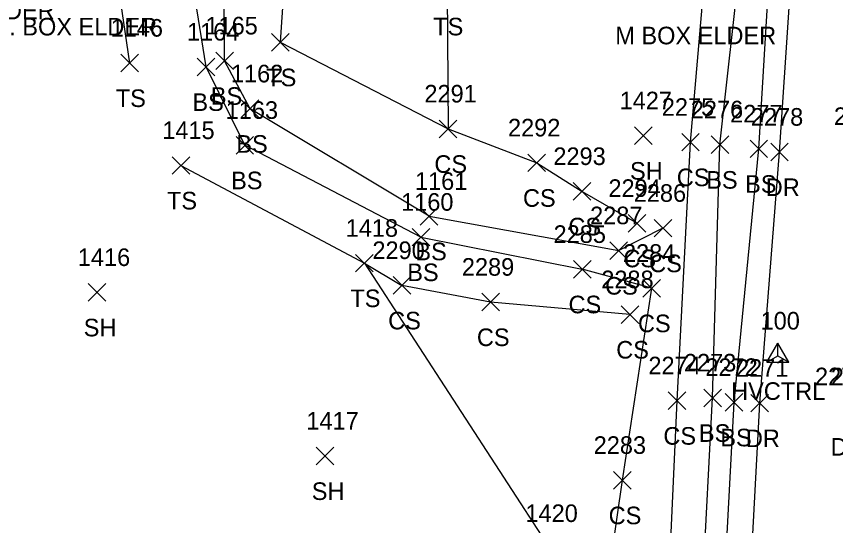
# Model space of a CAD drawing. Extents: x 1761340 to 1763889, y 696770 to 706023.
# Drawn here: x 1761564.7 to 1761657.7, y 700749.1 to 700807 of the extents above; entities that cross this region are included whole.
import ezdxf

# ---------------------------------------------------------------- set-up
doc = ezdxf.new("R2010")
doc.units = 0
for name, color, linetype in [('C_A', 7, 'Continuous'), ('C_I', 7, 'Continuous'), ('CPSM', 7, 'Continuous'), ('L_A', 7, 'Continuous'), ('L_C', 7, 'Continuous'), ('L_I', 7, 'Continuous'), ('L_TIC', 7, 'Continuous'), ('LELB', 7, 'Continuous'), ('R_A', 7, 'Continuous'), ('R_I', 7, 'Continuous'), ('R_TIC', 7, 'Continuous'), ('RDP', 7, 'Continuous')]:
    doc.layers.add(name, color=color, linetype=linetype)

msp = doc.modelspace()

# ---------------------------------------------------------------- linework, layer by layer
at = {"layer": 'CPSM'}
for p, q in [((1761649.911, 700767.711), (1761651.161, 700769.877)), ((1761652.411, 700767.711), (1761651.161, 700769.877)), ((1761651.161, 700768.433), (1761651.161, 700769.877)), ((1761649.911, 700767.711), (1761651.161, 700768.433)), ((1761651.161, 700768.433), (1761651.161, 700768.433)), ((1761651.161, 700768.433), (1761652.411, 700767.711)), ((1761649.911, 700767.711), (1761652.411, 700767.711))]:
    msp.add_line(p, q, dxfattribs=at)
at = {"layer": 'L_TIC'}
for points in [[(1761593.635, 700803.09), (1761595.635, 700805.09)], [(1761595.635, 700803.09), (1761593.635, 700805.09)], [(1761576.539, 700800.73), (1761578.539, 700802.73)], [(1761578.539, 700800.73), (1761576.539, 700802.73)], [(1761587.305, 700800.978), (1761589.305, 700802.978)], [(1761589.305, 700800.978), (1761587.305, 700802.978)], [(1761585.211, 700800.285), (1761587.211, 700802.285)], [(1761587.211, 700800.285), (1761585.211, 700802.285)], [(1761590.202, 700795.53), (1761592.202, 700797.53)], [(1761592.202, 700795.53), (1761590.202, 700797.53)], [(1761612.704, 700793.244), (1761614.704, 700795.244)], [(1761614.704, 700793.244), (1761612.704, 700795.244)], [(1761634.88, 700792.469), (1761636.88, 700794.469)], [(1761636.88, 700792.469), (1761634.88, 700794.469)], [(1761589.608, 700791.381), (1761591.608, 700793.381)], [(1761591.608, 700791.381), (1761589.608, 700793.381)], [(1761640.24, 700791.73), (1761642.24, 700793.73)], [(1761642.24, 700791.73), (1761640.24, 700793.73)], [(1761643.587, 700791.445), (1761645.587, 700793.445)], [(1761645.587, 700791.445), (1761643.587, 700793.445)], [(1761648.001, 700790.974), (1761650.001, 700792.974)], [(1761650.001, 700790.974), (1761648.001, 700792.974)], [(1761622.768, 700789.385), (1761624.768, 700791.385)], [(1761624.768, 700789.385), (1761622.768, 700791.385)], [(1761582.357, 700789.084), (1761584.357, 700791.084)], [(1761584.357, 700789.084), (1761582.357, 700791.084)], [(1761627.922, 700786.134), (1761629.922, 700788.134)], [(1761629.922, 700786.134), (1761627.922, 700788.134)], [(1761610.543, 700783.306), (1761612.543, 700785.306)], [(1761612.543, 700783.306), (1761610.543, 700785.306)], [(1761634.175, 700782.507), (1761636.175, 700784.507)], [(1761636.175, 700782.507), (1761634.175, 700784.507)], [(1761637.106, 700781.952), (1761639.106, 700783.952)], [(1761639.106, 700781.952), (1761637.106, 700783.952)], [(1761609.621, 700780.935), (1761611.621, 700782.935)], [(1761611.621, 700780.935), (1761609.621, 700782.935)], [(1761632.093, 700779.401), (1761634.093, 700781.401)], [(1761634.093, 700779.401), (1761632.093, 700781.401)], [(1761603.192, 700777.978), (1761605.192, 700779.978)], [(1761605.192, 700777.978), (1761603.192, 700779.978)], [(1761627.942, 700777.277), (1761629.942, 700779.277)], [(1761629.942, 700777.277), (1761627.942, 700779.277)], [(1761607.451, 700775.445), (1761609.451, 700777.445)], [(1761609.451, 700775.445), (1761607.451, 700777.445)], [(1761572.818, 700774.652), (1761574.818, 700776.652)], [(1761574.818, 700774.652), (1761572.818, 700776.652)], [(1761635.829, 700775.127), (1761637.829, 700777.127)], [(1761637.829, 700775.127), (1761635.829, 700777.127)], [(1761617.533, 700773.55), (1761619.533, 700775.55)], [(1761619.533, 700773.55), (1761617.533, 700775.55)], [(1761633.362, 700772.129), (1761635.362, 700774.129)], [(1761635.362, 700772.129), (1761633.362, 700774.129)], [(1761642.749, 700762.66), (1761644.749, 700764.66)], [(1761644.749, 700762.66), (1761642.749, 700764.66)], [(1761638.717, 700762.338), (1761640.717, 700764.338)], [(1761640.717, 700762.338), (1761638.717, 700764.338)], [(1761645.185, 700762.151), (1761647.185, 700764.151)], [(1761647.185, 700762.151), (1761645.185, 700764.151)], [(1761598.725, 700756.053), (1761600.725, 700758.053)], [(1761600.725, 700756.053), (1761598.725, 700758.053)], [(1761632.499, 700753.293), (1761634.499, 700755.293)], [(1761634.499, 700753.293), (1761632.499, 700755.293)]]:
    msp.add_lwpolyline(points, dxfattribs=at)
at = {"layer": 'LELB'}
for points in [[(1761650.668, 700568.581), (1761653.72, 700589.345), (1761656.228, 700611.846), (1761650.783, 700645.878), (1761646.693, 700682.268), (1761643.965, 700721.139), (1761646.185, 700763.151), (1761649.001, 700791.974), (1761651.08, 700826.684), (1761655.56, 700862.863), (1761665.437, 700900.351), (1761673.527, 700937.717), (1761682.384, 700964.347), (1761693.002, 701008.082), (1761690.127, 701015.338), (1761683.006, 701019.111)], [(1761647.361, 700568.693), (1761651.507, 700589.637), (1761652.179, 700611.172), (1761648.147, 700645.92), (1761644.284, 700683.035), (1761641.556, 700721.375), (1761643.749, 700763.66), (1761644.587, 700792.445), (1761648.472, 700827.402), (1761652.737, 700863.508), (1761659.58, 700901.674), (1761670.104, 700938.531), (1761679.505, 700964.488), (1761691.194, 701008.19), (1761682.174, 701016.504)], [(1761650.212, 700590.246), (1761648.805, 700610.457), (1761644.582, 700645.542), (1761640.712, 700682.502), (1761639.82, 700689.73), (1761639.14, 700693.979), (1761637.85, 700721.718), (1761639.717, 700763.338), (1761641.24, 700792.73), (1761643.277, 700816.475), (1761646.043, 700834.747), (1761651.107, 700867.028), (1761649.907, 700870.225), (1761650.052, 700873.461)], [(1761577.539, 700801.73), (1761575.514, 700815.635), (1761575.59, 700833.986), (1761577.556, 700840.879), (1761581.517, 700842.64), (1761585.93, 700841.056), (1761592.344, 700829.236), (1761595.734, 700820.511), (1761594.635, 700804.09)], [(1761610.621, 700781.935), (1761590.608, 700792.381), (1761586.211, 700801.285), (1761584.094, 700814.53), (1761578.1, 700827.586), (1761581.934, 700840.174), (1761583.885, 700839.339)], [(1761611.543, 700784.306), (1761591.202, 700796.53), (1761588.305, 700801.978), (1761588.217, 700817.541), (1761582.546, 700828.727), (1761583.885, 700839.339)], [(1761613.605, 700809.874), (1761613.704, 700794.244)], [(1761594.635, 700804.09), (1761613.704, 700794.244)], [(1761613.704, 700794.244), (1761623.768, 700790.385), (1761628.922, 700787.134), (1761635.175, 700783.507)], [(1761583.357, 700790.084), (1761604.192, 700778.978), (1761625.266, 700746.546), (1761630.344, 700732.213)], [(1761611.543, 700784.306), (1761633.093, 700780.401)], [(1761638.106, 700782.952), (1761633.093, 700780.401)], [(1761610.621, 700781.935), (1761628.942, 700778.277)], [(1761604.192, 700778.978), (1761608.451, 700776.445)], [(1761633.499, 700754.293), (1761636.829, 700776.127), (1761628.942, 700778.277)], [(1761634.362, 700773.129), (1761618.533, 700774.55), (1761608.451, 700776.445)], [(1761630.344, 700732.213), (1761633.499, 700754.293)]]:
    msp.add_lwpolyline(points, dxfattribs=at)
at = {"layer": 'R_TIC'}
for points in [[(1761650.354, 700790.608), (1761652.354, 700792.608)], [(1761652.354, 700790.608), (1761650.354, 700792.608)], [(1761648.099, 700762.058), (1761650.099, 700764.058)], [(1761650.099, 700762.058), (1761648.099, 700764.058)]]:
    msp.add_lwpolyline(points, dxfattribs=at)
at = {"layer": 'RDP'}
msp.add_lwpolyline([(1761671.259, 700538.434), (1761661.644, 700574.622), (1761657.605, 700611.792), (1761653.176, 700645.742), (1761649.934, 700682.027), (1761646.901, 700721.235), (1761649.099, 700763.058), (1761651.354, 700791.608), (1761653.655, 700826.216), (1761659.48, 700861.884), (1761668.314, 700899.372), (1761676.768, 700936.595), (1761684.872, 700963.935), (1761695.512, 701007.432), (1761695.754, 701009.139), (1761702.957, 701038.717), (1761714.691, 701083.389), (1761730.248, 701133.725)], dxfattribs=at)

# ---------------------------------------------------------------- texts
at = {"layer": 'C_A'}
msp.add_text('HVCTRL', height=2, dxfattribs=at).set_placement((1761645.854, 700763.433))
at = {"layer": 'C_I'}
msp.add_text('100', height=2, dxfattribs=at).set_placement((1761649.201, 700771.433))
at = {"layer": 'L_A'}
for s, p in [('TS', (1761612.014, 700804.874)), ('TS', (1761593.044, 700799.09)), ('BS', (1761586.746, 700796.978)), ('TS', (1761575.948, 700796.73)), ('BS', (1761584.652, 700796.285)), ('BS', (1761589.643, 700791.53)), ('CS', (1761612.145, 700789.244)), ('SH', (1761634.368, 700788.469)), ('CS', (1761639.681, 700787.73)), ('BS', (1761589.049, 700787.381)), ('BS', (1761643.028, 700787.445)), ('BS', (1761647.442, 700786.974)), ('TS', (1761581.766, 700785.084)), ('CS', (1761622.209, 700785.385)), ('CS', (1761627.363, 700782.134)), ('BS', (1761609.984, 700779.306)), ('CS', (1761633.616, 700778.507)), ('CS', (1761636.546, 700777.952)), ('BS', (1761609.062, 700776.935)), ('CS', (1761631.534, 700775.401)), ('TS', (1761602.601, 700773.978)), ('CS', (1761627.383, 700773.277)), ('CS', (1761606.892, 700771.445)), ('CS', (1761635.27, 700771.127)), ('SH', (1761572.306, 700770.652)), ('CS', (1761616.974, 700769.55)), ('CS', (1761632.803, 700768.129)), ('BS', (1761642.19, 700758.66)), ('CS', (1761638.158, 700758.338)), ('BS', (1761644.626, 700758.151)), ('SH', (1761598.214, 700752.053)), ('CS', (1761631.94, 700749.293))]:
    msp.add_text(s, height=2, dxfattribs=at).set_placement(p)
at = {"layer": 'L_C'}
for s, p in [('M. BOX ELDER', (1761549.984, 700806.69)), ('M. BOX ELDER', (1761561.615, 700804.867)), ('M BOX ELDER', (1761632.694, 700803.858))]:
    msp.add_text(s, height=2, dxfattribs=at).set_placement(p)
at = {"layer": 'L_I'}
for s, p in [('1146', (1761575.358, 700804.73)), ('1164', (1761584.038, 700804.285)), ('1165', (1761586.132, 700804.978)), ('1162', (1761589.029, 700799.53)), ('2291', (1761611.011, 700797.244)), ('1427', (1761633.187, 700796.469)), ('1163', (1761588.435, 700795.381)), ('2275', (1761637.981, 700795.73)), ('2276', (1761641.272, 700795.445)), ('2277', (1761645.742, 700794.974)), ('1415', (1761581.231, 700793.084)), ('2292', (1761620.508, 700793.385)), ('2293', (1761625.662, 700790.134)), ('1161', (1761609.937, 700787.306)), ('2294', (1761631.916, 700786.507)), ('2286', (1761634.791, 700785.952)), ('1160', (1761608.362, 700784.935)), ('2287', (1761629.833, 700783.401)), ('1418', (1761602.066, 700781.978)), ('2285', (1761625.683, 700781.277)), ('2290', (1761605.105, 700779.445)), ('2284', (1761633.569, 700779.127)), ('1416', (1761571.637, 700778.652)), ('2289', (1761615.265, 700777.55)), ('2288', (1761631.103, 700776.129)), ('2274', (1761636.457, 700766.338)), ('2273', (1761640.489, 700766.66)), ('2272', (1761642.925, 700766.151)), ('2269', (1761657.18, 700765.081)), ('1417', (1761597.6, 700760.053)), ('2283', (1761630.24, 700757.293)), ('1420', (1761622.487, 700749.546))]:
    msp.add_text(s, height=2, dxfattribs=at).set_placement(p)
at = {"layer": 'R_A'}
for p in [(1761649.787, 700786.608), (1761647.532, 700758.058), (1761657.166, 700757.092)]:
    msp.add_text('DR', height=2, dxfattribs=at).set_placement(p)
at = {"layer": 'R_I'}
for s, p in [('2278', (1761648.095, 700794.608)), ('2279', (1761657.534, 700794.687)), ('2271', (1761646.406, 700766.058)), ('2270', (1761655.386, 700765.092))]:
    msp.add_text(s, height=2, dxfattribs=at).set_placement(p)

doc.saveas('drawing.dxf')
